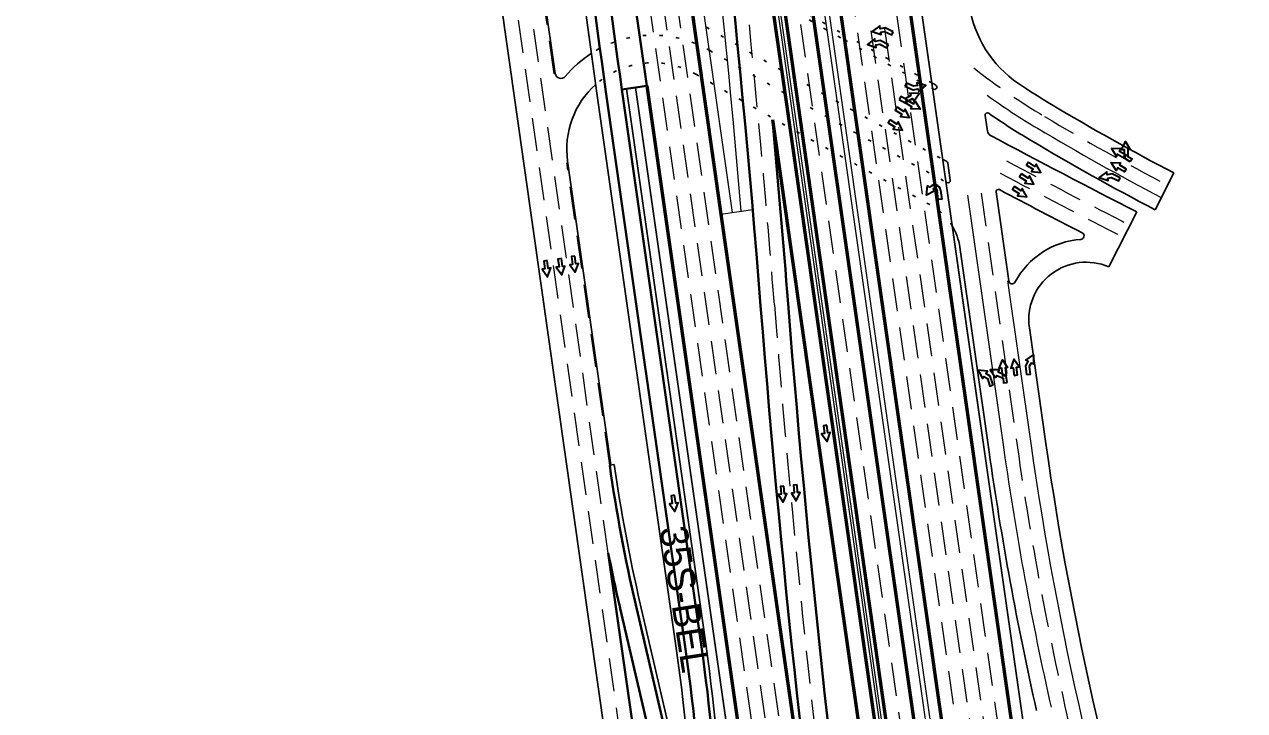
# Model space of a CAD drawing. Extents: x 2329387 to 2347382, y 6951580 to 6987999.
# Drawn here: x 2330631 to 2331694, y 6969457 to 6970054 of the extents above; entities that cross this region are included whole.
import ezdxf

# ---------------------------------------------------------------- set-up
doc = ezdxf.new("R2010")
doc.units = 0
doc.header["$LTSCALE"] = 9.6
doc.linetypes.add('DOTTED', pattern=[1.5, 0.3, -1.2])
doc.linetypes.add('MEDIUM_DASHED', pattern=[4.5, 3, -1.5])
for name, color, linetype, lineweight in [('26', 7, 'Continuous', 53), ('27', 7, 'Continuous', 40), ('28', 7, 'Continuous', 25), ('30', 7, 'Continuous', 13), ('31', 7, 'Continuous', 53), ('41', 7, 'Continuous', 35), ('50', 7, 'MEDIUM_DASHED', 13)]:
    doc.layers.add(name, color=color, linetype=linetype, lineweight=lineweight)
doc.layers.add('40', color=7, linetype='Continuous')

msp = doc.modelspace()

# ---------------------------------------------------------------- linework, layer by layer
at = {"layer": '26'}
for p, q in [((2330667.024, 6973887.048), (2331238.034, 6969888.911)), ((2331204.547, 6971028.714), (2331531.518, 6968739.307)), ((2331305.118, 6970748.901), (2331509.335, 6969318.999)), ((2331173.611, 6970000.486), (2331352.172, 6968750.231))]:
    msp.add_line(p, q, dxfattribs=at)
at = {"layer": '26', "lineweight": 13}
for p, q in [((2330676.924, 6973888.462), (2331247.933, 6969890.325)), ((2331194.647, 6971027.301), (2331508.441, 6968830.155))]:
    msp.add_line(p, q, dxfattribs=at)
at = {"layer": '26', "lineweight": 25}
for p, q in [((2331299.907, 6970856.121), (2331540.622, 6969170.663)), ((2331163.712, 6969999.072), (2331342.272, 6968748.817))]:
    msp.add_line(p, q, dxfattribs=at)
at = {"layer": '27'}
for p, q in [((2331098.035, 6970529.663), (2331173.611, 6970000.486)), ((2331137.973, 6969995.396), (2331207.287, 6969510.069)), ((2331173.611, 6970000.486), (2331151.832, 6969997.376)), ((2331151.832, 6969997.376), (2331221.146, 6969512.049)), ((2331170.338, 6969380.127), (2331139.96, 6969593.801)), ((2331217.589, 6969256.243), (2331150.298, 6969545.603)), ((2331214.872, 6969329.735), (2331163.934, 6969548.774))]:
    msp.add_line(p, q, dxfattribs=at)
at = {"layer": '27', "lineweight": 25}
for p, q in [((2331130.053, 6969994.265), (2331199.367, 6969508.938)), ((2331155.792, 6969997.941), (2331225.106, 6969512.614)), ((2331141.19, 6969670.405), (2331145.15, 6969670.968)), ((2331214.085, 6969350.778), (2331167.83, 6969549.68))]:
    msp.add_line(p, q, dxfattribs=at)
at = {"layer": '27'}
for centre, radius, start, end in [((2336809.996, 6970805.468), 5729.578, 183.84506, 188.12795), ((2336809.996, 6970805.468), 5715.578, 183.84506, 188.12795), ((2332545.464, 6969870.051), 1418.395, 188.09153, 193.09153), ((2332545.464, 6969870.051), 1432.395, 191.11964, 193.09153), ((2329586.709, 6969278.62), 1637.022, 2.05953, 8.12795), ((2329586.709, 6969278.62), 1651.022, 2.6386, 8.12795)]:
    msp.add_arc(centre, radius, start, end, dxfattribs=at)
at = {"layer": '27', "lineweight": 25}
for centre, radius, start, end in [((2336809.996, 6970805.468), 5737.578, 184.02938, 188.12795), ((2332545.464, 6969870.051), 1414.395, 188.09153, 193.09153), ((2329586.709, 6969278.62), 1629.022, 2.05953, 8.12795), ((2329586.709, 6969278.62), 1655.022, 2.05953, 8.12795)]:
    msp.add_arc(centre, radius, start, end, dxfattribs=at)
at = {"layer": '28'}
for p, q in [((2331093.742, 6970011.248), (2331078.312, 6970119.784)), ((2331390.789, 6967651.904), (2331040.416, 6970116.36)), ((2331468.203, 6969974.794), (2331470.154, 6969961.133)), ((2331142.18, 6969670.545), (2331104.569, 6969935.098)), ((2331435.755, 6969933.221), (2331437.862, 6969918.466)), ((2331632.476, 6969924.742), (2331616.181, 6969892.669)), ((2331477.722, 6969908.147), (2331488.769, 6969830.793)), ((2331575.942, 6969842.95), (2331600.356, 6969890.799)), ((2331441.833, 6969862.375), (2331464.402, 6969704.344)), ((2331446.209, 6969860.022), (2331471.631, 6969682.025)), ((2331506.727, 6969789.933), (2331521.128, 6969689.094))]:
    msp.add_line(p, q, dxfattribs=at)
at = {"layer": '28', "linetype": 'DOTTED'}
for centre, radius, start, end in [((2335078.828, 6976708.081), 7637.437, 238.95455, 240.72986), ((2335078.828, 6976708.081), 7641.437, 238.97898, 240.75681), ((2335078.828, 6976708.081), 7691.437, 238.96852, 241.69007), ((2331178.822, 6969945.654), 99, 60.02722, 122.78367), ((2335078.828, 6976708.081), 7637.437, 240.7224, 241.39041), ((2335078.828, 6976708.081), 7641.437, 240.75681, 241.41279), ((2335078.828, 6976708.081), 7707.437, 240.02722, 241.77783), ((2331178.822, 6969945.654), 75, 60.02722, 131.6376), ((2335078.828, 6976708.081), 7731.437, 240.02722, 241.75828), ((2331396.711, 6969852.953), 50, 31.20187, 61.75828)]:
    msp.add_arc(centre, radius, start, end, dxfattribs=at)
at = {"layer": '28'}
for centre, radius, start, end in [((2331553.434, 6970085.308), 100, 188.12795, 235.83752), ((2331178.822, 6969945.654), 99, 122.78367, 140.39652), ((2331098.693, 6970011.951), 5, 188.09153, 320.39652), ((2331178.822, 6969945.654), 75, 131.63759, 188.09153), ((2335078.828, 6976708.081), 7637.437, 241.39041, 241.42031), ((2331820.728, 6970479.174), 576, 235.83752, 239.23121), ((2335078.828, 6976708.081), 7641.437, 241.41279, 241.42031), ((2331424.27, 6969999.489), 2, 241.42031, 8.12795), ((2331424.27, 6969999.489), 2, 8.12795, 61.42031), ((2332666.846, 6971900.309), 2229.947, 239.23121, 242.36805), ((2331470.183, 6969975.076), 2, 55.18558, 188.12795), ((2331820.728, 6970479.174), 612, 235.18557, 239.23121), ((2331475.104, 6969961.84), 5, 188.12795, 241.88964), ((2335078.828, 6976708.081), 7653.437, 241.88964, 242.96736), ((2332666.846, 6971900.309), 2265.947, 239.23121, 242.37545), ((2335078.828, 6976708.081), 7691.437, 241.69007, 241.71957), ((2331433.775, 6969932.938), 2, 8.12795, 61.71957), ((2335078.828, 6976708.081), 7707.437, 241.77783, 241.78535), ((2331435.882, 6969918.184), 2, 241.78535, 8.12795), ((2331479.702, 6969908.429), 2, 62.10726, 188.12795), ((2335078.828, 6976708.081), 7691.437, 242.10726, 242.71347), ((2331396.711, 6969852.953), 50, 8.12795, 31.20187), ((2331556.224, 6969797.002), 70, 93.80018, 152.05026), ((2331551.386, 6969869.842), 3, 273.80018, 62.71347), ((2331556.224, 6969797.002), 50, 66.77489, 188.12795), ((2331491.739, 6969831.217), 3, 188.12795, 332.05026), ((2334356.15, 6970093.989), 2863.789, 188.12795, 197.82748), ((2334356.15, 6970093.989), 2913.789, 188.12795, 192.63567)]:
    msp.add_arc(centre, radius, start, end, dxfattribs=at)
at = {"layer": '30', "lineweight": 53}
for p, q in [((2330735.905, 6973899.861), (2331296.241, 6969976.458)), ((2330745.804, 6973901.275), (2331470.823, 6968824.782)), ((2331004.304, 6972261.043), (2331494.582, 6968828.175)), ((2331238.034, 6969888.911), (2331352.7, 6969086.035))]:
    msp.add_line(p, q, dxfattribs=at)
at = {"layer": '30'}
for p, q in [((2330739.864, 6973900.426), (2331300.2, 6969977.023)), ((2330741.844, 6973900.709), (2331466.866, 6968824.195)), ((2331014.231, 6972262.259), (2331504.482, 6968829.589)), ((2331238.034, 6969888.911), (2331265.768, 6969892.872))]:
    msp.add_line(p, q, dxfattribs=at)
msp.add_arc((2319808.196, 6968905.935), 11490, 4.92042, 8.12795, dxfattribs=at)
at = {"layer": '30', "lineweight": 40}
for centre, radius, start, end in [((2319808.196, 6968905.935), 11500, 4.50364, 8.12795), ((2319808.196, 6968905.935), 11524, 4.50364, 5.30344), ((2342737.18, 6970711.953), 11476, 184.50364, 188.12795), ((2342737.18, 6970711.953), 11500, 184.50364, 188.12795)]:
    msp.add_arc(centre, radius, start, end, dxfattribs=at)
at = {"layer": '31'}
for p, q in [((2331282.863, 6969971.102), (2331333.019, 6969619.916)), ((2331296.241, 6969976.458), (2331690.26, 6967217.584)), ((2331333.019, 6969619.916), (2331676.4, 6967215.605))]:
    msp.add_line(p, q, dxfattribs=at)
at = {"layer": '31', "lineweight": 13}
msp.add_line((2331300.2, 6969977.023), (2331694.22, 6967218.149), dxfattribs=at)
at = {"layer": '41'}
for points in [[(2331388.161, 6970047.558), (2331381.073, 6970051.145), (2331376.775, 6970050.274), (2331376.386, 6970052.68), (2331369.882, 6970047.8), (2331377.593, 6970045.219), (2331377.254, 6970047.311), (2331380.645, 6970047.999), (2331386.806, 6970044.881)], [(2331383.908, 6970036.389), (2331376.82, 6970039.977), (2331372.522, 6970039.105), (2331372.133, 6970041.511), (2331365.628, 6970036.631), (2331373.339, 6970034.05), (2331373.001, 6970036.143), (2331376.392, 6970036.83), (2331382.553, 6970033.712)], [(2331398.362, 6970000.299), (2331405.591, 6969997.004), (2331409.85, 6969998.051), (2331410.337, 6969995.663), (2331416.636, 6970000.805), (2331408.826, 6970003.068), (2331409.25, 6970000.991), (2331405.89, 6970000.165), (2331399.607, 6970003.029)], [(2331393.294, 6969988.677), (2331398.538, 6969985.792), (2331404.969, 6969989.528), (2331406.067, 6969987.352), (2331410.793, 6969993.969), (2331402.662, 6969994.099), (2331403.617, 6969992.207), (2331398.42, 6969989.245), (2331394.787, 6969991.312)], [(2331391.567, 6969982.031), (2331389.951, 6969979.504), (2331395.685, 6969975.836), (2331394.371, 6969973.783), (2331402.473, 6969973.086), (2331398.444, 6969980.149), (2331397.302, 6969978.364)], [(2331398.538, 6969985.792), (2331400.033, 6969988.394), (2331405.934, 6969985.002), (2331407.149, 6969987.115), (2331411.508, 6969980.251), (2331403.383, 6969980.563), (2331404.439, 6969982.4)], [(2331385.449, 6969970.98), (2331383.832, 6969968.452), (2331389.566, 6969964.785), (2331388.253, 6969962.731), (2331396.354, 6969962.035), (2331392.325, 6969969.098), (2331391.183, 6969967.313)], [(2331594.632, 6969934.413), (2331589.52, 6969937.524), (2331589.557, 6969944.961), (2331587.124, 6969944.83), (2331590.509, 6969952.223), (2331594.67, 6969945.237), (2331592.554, 6969945.123), (2331592.573, 6969939.141), (2331596.174, 6969937.02)], [(2331589.52, 6969937.524), (2331591.031, 6969940.116), (2331585.151, 6969943.545), (2331586.379, 6969945.651), (2331578.256, 6969946.014), (2331582.572, 6969939.122), (2331583.64, 6969940.953)], [(2331505.892, 6969934.137), (2331504.275, 6969931.61), (2331510.009, 6969927.942), (2331508.696, 6969925.889), (2331516.798, 6969925.192), (2331512.768, 6969932.255), (2331511.626, 6969930.47)], [(2331505.892, 6969934.137), (2331504.275, 6969931.61), (2331510.009, 6969927.942), (2331508.696, 6969925.889), (2331516.798, 6969925.192), (2331512.768, 6969932.255), (2331511.626, 6969930.47)], [(2331591.023, 6969928.217), (2331589.495, 6969925.634), (2331583.637, 6969929.1), (2331582.396, 6969927.002), (2331578.123, 6969933.92), (2331586.244, 6969933.507), (2331585.164, 6969931.683)], [(2331499.853, 6969923.994), (2331498.237, 6969921.467), (2331503.971, 6969917.799), (2331502.657, 6969915.746), (2331510.759, 6969915.049), (2331506.73, 6969922.112), (2331505.587, 6969920.327)], [(2331499.853, 6969923.994), (2331498.237, 6969921.467), (2331503.971, 6969917.799), (2331502.657, 6969915.746), (2331510.759, 6969915.049), (2331506.73, 6969922.112), (2331505.587, 6969920.327)], [(2331585.935, 6969920.447), (2331578.847, 6969924.034), (2331574.549, 6969923.163), (2331574.16, 6969925.569), (2331567.655, 6969920.689), (2331575.366, 6969918.108), (2331575.028, 6969920.2), (2331578.419, 6969920.888), (2331584.58, 6969917.769)], [(2331493.734, 6969912.943), (2331492.118, 6969910.415), (2331497.852, 6969906.748), (2331496.538, 6969904.694), (2331504.64, 6969903.998), (2331500.611, 6969911.061), (2331499.469, 6969909.276)], [(2331493.734, 6969912.943), (2331492.118, 6969910.415), (2331497.852, 6969906.748), (2331496.538, 6969904.694), (2331504.64, 6969903.998), (2331500.611, 6969911.061), (2331499.469, 6969909.276)], [(2331086.743, 6969848.409), (2331083.774, 6969847.975), (2331084.757, 6969841.24), (2331082.345, 6969840.888), (2331087.124, 6969834.309), (2331089.823, 6969841.979), (2331087.726, 6969841.673)], [(2331099.11, 6969850.132), (2331096.141, 6969849.698), (2331097.124, 6969842.963), (2331094.712, 6969842.611), (2331099.492, 6969836.032), (2331102.191, 6969843.702), (2331100.093, 6969843.396)], [(2331110.851, 6969852.304), (2331107.881, 6969851.871), (2331108.865, 6969845.135), (2331106.453, 6969844.783), (2331111.232, 6969838.205), (2331113.931, 6969845.875), (2331111.834, 6969845.569)], [(2331486.513, 6969748.2), (2331483.533, 6969747.85), (2331482.74, 6969754.611), (2331480.319, 6969754.327), (2331483.234, 6969761.918), (2331487.826, 6969755.207), (2331485.721, 6969754.96)], [(2331493.507, 6969748.415), (2331496.48, 6969748.824), (2331495.554, 6969755.567), (2331497.969, 6969755.899), (2331493.245, 6969762.518), (2331490.481, 6969754.87), (2331492.581, 6969755.159)], [(2331504.533, 6969748.954), (2331503.552, 6969756.837), (2331505.825, 6969760.587), (2331503.692, 6969761.767), (2331510.483, 6969766.239), (2331510.306, 6969758.11), (2331508.451, 6969759.135), (2331506.658, 6969756.177), (2331507.511, 6969749.324)], [(2331475.261, 6969740.174), (2331472.62, 6969747.666), (2331468.912, 6969750.007), (2331470.294, 6969752.015), (2331462.221, 6969752.986), (2331466.008, 6969745.79), (2331467.21, 6969747.536), (2331470.135, 6969745.689), (2331472.431, 6969739.176)], [(2331487.321, 6969742.27), (2331486.513, 6969748.2), (2331479.681, 6969751.138), (2331480.774, 6969753.316), (2331472.644, 6969753.169), (2331477.384, 6969746.562), (2331478.335, 6969748.456), (2331483.811, 6969746.048), (2331484.315, 6969741.899)], [(2331330.262, 6969705.089), (2331327.29, 6969704.676), (2331328.227, 6969697.934), (2331325.812, 6969697.598), (2331330.546, 6969690.987), (2331333.298, 6969698.638), (2331331.199, 6969698.347)], [(2331292.919, 6969652.072), (2331289.926, 6969651.854), (2331290.421, 6969645.065), (2331287.99, 6969644.888), (2331292.283, 6969637.982), (2331295.528, 6969645.438), (2331293.414, 6969645.283)], [(2331304.388, 6969653.185), (2331301.395, 6969652.967), (2331301.89, 6969646.178), (2331299.459, 6969646.001), (2331303.752, 6969639.095), (2331306.997, 6969646.551), (2331304.883, 6969646.396)], [(2331197.778, 6969644.044), (2331194.806, 6969643.631), (2331195.743, 6969636.889), (2331193.328, 6969636.554), (2331198.062, 6969629.942), (2331200.814, 6969637.594), (2331198.715, 6969637.302)]]:
    msp.add_lwpolyline(points, close=True, dxfattribs=at)
for points in [[(2331422.65, 6969910.437), (2331424.4, 6969909.255), (2331417.238, 6969905.403), (2331418.137, 6969913.485), (2331420.156, 6969912.121)], [(2331429.345, 6969909.802), (2331430.381, 6969901.926), (2331427.406, 6969901.534), (2331426.342, 6969909.624), (2331426.347, 6969909.575)]]:
    msp.add_lwpolyline(points, dxfattribs=at)
for radius, end in [(4.997, 147.33741), (1.989, 149.41123)]:
    msp.add_arc((2331424.363, 6969909.424), radius, 4.33259, end, dxfattribs=at)
at = {"layer": '50'}
for p, q in [((2330757.684, 6973902.971), (2331482.703, 6968826.479)), ((2330631.386, 6973881.958), (2331606.386, 6967055.128)), ((2330643.265, 6973883.655), (2331618.272, 6967056.781)), ((2330655.145, 6973885.352), (2331630.147, 6967058.504)), ((2331240.185, 6971033.804), (2331567.156, 6968744.397)), ((2331216.426, 6971030.411), (2331543.397, 6968741.003)), ((2331228.306, 6971032.108), (2331555.277, 6968742.7)), ((2331637.49, 6966009.015), (2330956.52, 6970798.829)), ((2331139.96, 6969593.801), (2330968.401, 6970800.518)), ((2331293.239, 6970747.205), (2331541.861, 6969006.386)), ((2331092.752, 6970011.107), (2331077.322, 6970119.643)), ((2331141.19, 6969670.405), (2331103.799, 6969933.407)), ((2331464.749, 6969907.028), (2331496.379, 6969685.56))]:
    msp.add_line(p, q, dxfattribs=at)
at = {"layer": '50', "linetype": 'Continuous'}
for p, q in [((2331452.87, 6969905.332), (2331484.5, 6969683.863)), ((2331487.779, 6969830.652), (2331508.259, 6969687.256))]:
    msp.add_line(p, q, dxfattribs=at)
at = {"layer": '50'}
for centre, radius, start, end in [((2319808.196, 6968905.935), 11512, 4.50364, 8.12795), ((2331820.728, 6970479.174), 588, 231.94201, 239.23121), ((2332666.846, 6971900.309), 2241.947, 239.23121, 242.36805), ((2335078.828, 6976708.081), 7666.437, 242.06191, 242.96736), ((2335078.828, 6976708.081), 7678.437, 242.06191, 242.96736), ((2342737.18, 6970711.953), 11488, 184.50364, 188.12795), ((2334356.15, 6970093.989), 2888.789, 188.12795, 197.82748)]:
    msp.add_arc(centre, radius, start, end, dxfattribs=at)
at = {"layer": '50', "linetype": 'Continuous'}
for centre, radius, start, end in [((2331820.728, 6970479.174), 600, 234.23663, 239.23121), ((2332666.846, 6971900.309), 2253.947, 239.23121, 242.37177), ((2334356.15, 6970093.989), 2900.789, 188.12795, 192.63567), ((2334356.15, 6970093.989), 2876.789, 188.12795, 197.82748)]:
    msp.add_arc(centre, radius, start, end, dxfattribs=at)

# ---------------------------------------------------------------- texts
at = {"layer": '40'}
msp.add_text('35S-BEL', height=24, rotation=278.89, dxfattribs=at).set_placement((2331184.68, 6969615.278))

doc.saveas('drawing.dxf')
